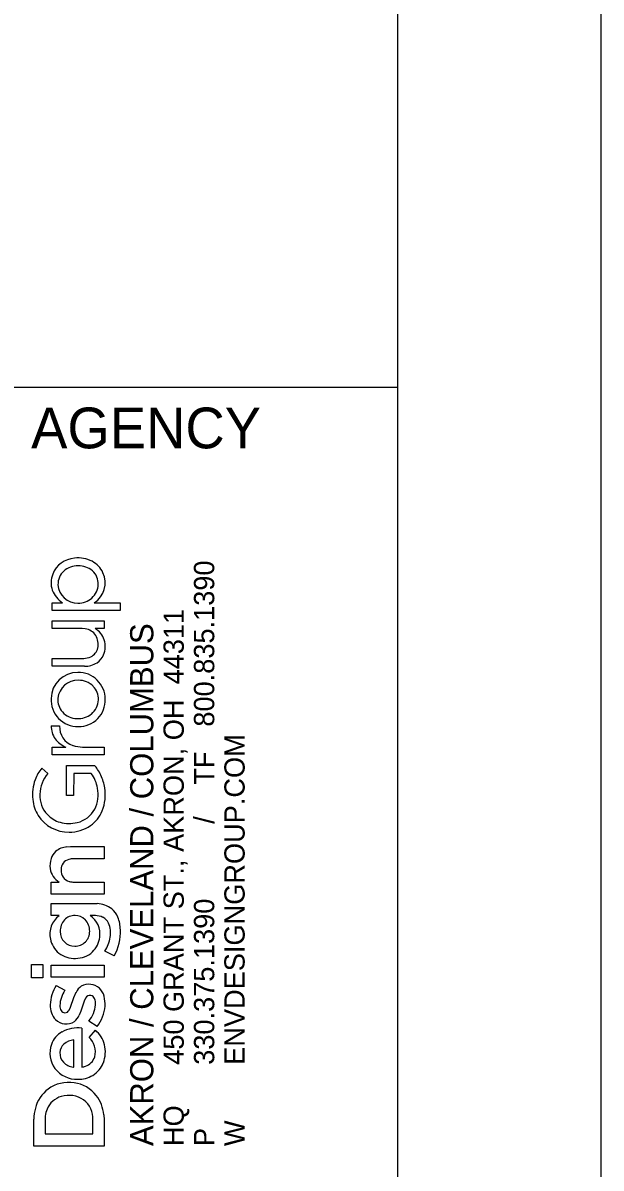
# Model space of a CAD drawing. Extents: x 0 to 34, y 0 to 22.
# Drawn here: x 32.58 to 34, y 2.584 to 5.394 of the extents above; entities that cross this region are included whole.
import ezdxf

# ---------------------------------------------------------------- set-up
doc = ezdxf.new("R2010")
doc.units = 0
for name, color, linetype in [('SH_Border', 7, 'Continuous'), ('SH_Cut_Line', 7, 'Continuous'), ('SH_Data', 7, 'Continuous')]:
    doc.layers.add(name, color=color, linetype=linetype)

msp = doc.modelspace()

# ---------------------------------------------------------------- linework, layer by layer
at = {"layer": 'SH_Border'}
msp.add_line((32, 4.5), (33.5, 4.5), dxfattribs=at)
msp.add_lwpolyline([(1.5, 21.5), (33.5, 21.5), (33.5, 0.5), (1.5, 0.5)], close=True, dxfattribs=at)
at = {"layer": 'SH_Cut_Line'}
msp.add_lwpolyline([(0, 0), (34, 0), (34, 22), (0, 22)], close=True, dxfattribs=at)
at = {"layer": 'SH_Data'}
for p, q in [((32.6515, 3.9521), (32.6515, 3.9711)), ((32.6515, 3.9711), (32.6771, 3.9711)), ((32.7549, 3.9713), (32.8186, 3.9711)), ((32.8186, 3.9711), (32.8184, 3.9521)), ((32.8184, 3.9521), (32.6515, 3.9521)), ((32.6515, 3.908), (32.6515, 3.9267)), ((32.6515, 3.9267), (32.7791, 3.9266)), ((32.7249, 3.908), (32.6515, 3.908)), ((32.7328, 3.9073), (32.7249, 3.908)), ((32.7791, 3.908), (32.7569, 3.908)), ((32.7791, 3.9266), (32.7791, 3.908)), ((32.6515, 3.8344), (32.7291, 3.8345)), ((32.6517, 3.8154), (32.6515, 3.8344)), ((32.7307, 3.8154), (32.6517, 3.8154)), ((32.6493, 3.6691), (32.6698, 3.6691)), ((32.6515, 3.598), (32.6515, 3.617)), ((32.6515, 3.617), (32.6848, 3.617)), ((32.779, 3.598), (32.6515, 3.598)), ((32.726, 3.617), (32.7791, 3.617)), ((32.7791, 3.617), (32.779, 3.598)), ((32.6868, 3.5718), (32.7552, 3.5719)), ((32.6868, 3.4978), (32.6868, 3.5718)), ((32.6264, 3.5655), (32.6411, 3.5524)), ((32.7045, 3.5524), (32.7043, 3.4978)), ((32.7474, 3.5523), (32.7045, 3.5524)), ((32.7043, 3.4978), (32.6868, 3.4978)), ((32.75, 3.5), (32.75, 3.5)), ((32.6878, 3.3722), (32.6963, 3.3727)), ((32.6963, 3.3727), (32.7792, 3.3727)), ((32.7792, 3.3727), (32.7792, 3.3429)), ((32.7792, 3.3429), (32.7048, 3.3428)), ((32.6489, 3.2557), (32.6489, 3.2855)), ((32.6489, 3.2855), (32.669, 3.2855)), ((32.7057, 3.2855), (32.7791, 3.2855)), ((32.7791, 3.2855), (32.7792, 3.2558)), ((32.7792, 3.2558), (32.6489, 3.2557)), ((32.6489, 3.2034), (32.6489, 3.2332)), ((32.6489, 3.2332), (32.7524, 3.2332)), ((32.7524, 3.2332), (32.7619, 3.2329)), ((32.6684, 3.2034), (32.6489, 3.2034)), ((32.7576, 3.2036), (32.7449, 3.2036)), ((32.8036, 3.1049), (32.7812, 3.116)), ((32.6005, 3.0511), (32.6005, 3.0832)), ((32.6005, 3.0832), (32.6289, 3.0832)), ((32.6289, 3.0832), (32.6289, 3.0511)), ((32.6489, 3.0523), (32.6489, 3.0822)), ((32.6489, 3.0822), (32.7792, 3.0822)), ((32.7792, 3.0822), (32.7792, 3.0523)), ((32.6289, 3.0511), (32.6005, 3.0511)), ((32.7792, 3.0523), (32.6489, 3.0523)), ((32.6615, 3.0321), (32.6827, 3.0203)), ((32.7048, 3.0026), (32.7104, 3.0153)), ((32.693, 2.9712), (32.6967, 2.9787)), ((32.6967, 2.9787), (32.7048, 3.0026)), ((32.7298, 2.9933), (32.7221, 2.9688)), ((32.7334, 3.001), (32.7298, 2.9933)), ((32.7221, 2.9688), (32.7182, 2.9592)), ((32.7245, 2.9275), (32.7246, 2.8319)), ((32.7621, 2.9314), (32.742, 2.9447)), ((32.7049, 2.8318), (32.7049, 2.8983)), ((32.7423, 2.9046), (32.7577, 2.922)), ((32.7036, 2.8317), (32.7049, 2.8318)), ((32.6064, 2.638), (32.6064, 2.704)), ((32.6347, 2.7118), (32.6341, 2.7023)), ((32.6341, 2.7023), (32.6341, 2.6684)), ((32.7515, 2.6683), (32.7515, 2.7024)), ((32.7785, 2.715), (32.7792, 2.7021)), ((32.7792, 2.7021), (32.7792, 2.638)), ((32.6341, 2.6684), (32.7515, 2.6683)), ((32.7792, 2.638), (32.6064, 2.638))]:
    msp.add_line(p, q, dxfattribs=at)
for points in [[(32.7549, 3.9713), (32.8186, 3.9711), (32.8184, 3.9521), (32.6515, 3.9521)], [(32.6515, 3.9521), (32.6515, 3.9711), (32.6771, 3.9711)], [(32.7328, 3.9073), (32.7249, 3.908), (32.6515, 3.908), (32.6515, 3.9267), (32.7791, 3.9266), (32.7791, 3.908), (32.7569, 3.908)], [(32.7307, 3.8154), (32.6517, 3.8154), (32.6515, 3.8344), (32.7291, 3.8345)], [(32.6493, 3.6691), (32.6698, 3.6691)], [(32.6515, 3.598), (32.6515, 3.617), (32.6848, 3.617)], [(32.726, 3.617), (32.7791, 3.617), (32.779, 3.598), (32.6515, 3.598)], [(32.7474, 3.5523), (32.7045, 3.5524), (32.7043, 3.4978), (32.6868, 3.4978), (32.6868, 3.5718), (32.7552, 3.5719)], [(32.6264, 3.5655), (32.6411, 3.5524)], [(32.6878, 3.3722), (32.6963, 3.3727), (32.7792, 3.3727), (32.7792, 3.3429), (32.7048, 3.3428)], [(32.6489, 3.2557), (32.6489, 3.2855), (32.669, 3.2855)], [(32.7057, 3.2855), (32.7791, 3.2855), (32.7792, 3.2558), (32.6489, 3.2557)], [(32.6684, 3.2034), (32.6489, 3.2034), (32.6489, 3.2332), (32.7524, 3.2332), (32.7619, 3.2329)], [(32.7576, 3.2036), (32.7449, 3.2036)], [(32.8036, 3.1049), (32.7812, 3.116)], [(32.6615, 3.0321), (32.6827, 3.0203)], [(32.693, 2.9712), (32.6967, 2.9787), (32.7048, 3.0026), (32.7104, 3.0153)], [(32.7334, 3.001), (32.7298, 2.9933), (32.7221, 2.9688), (32.7182, 2.9592)], [(32.7245, 2.9275), (32.7246, 2.8319)], [(32.7621, 2.9314), (32.742, 2.9447)], [(32.7036, 2.8317), (32.7049, 2.8318), (32.7049, 2.8983)], [(32.7423, 2.9046), (32.7577, 2.922)], [(32.7785, 2.715), (32.7792, 2.7021), (32.7792, 2.638), (32.6064, 2.638)], [(32.6064, 2.638), (32.6064, 2.704)], [(32.6347, 2.7118), (32.6341, 2.7023), (32.6341, 2.6684), (32.7515, 2.6683), (32.7515, 2.7024)]]:
    msp.add_lwpolyline(points, dxfattribs=at)
for points in [[(32.6005, 3.0511), (32.6005, 3.0832), (32.6289, 3.0832), (32.6289, 3.0511)], [(32.6489, 3.0523), (32.6489, 3.0822), (32.7792, 3.0822), (32.7792, 3.0523)]]:
    msp.add_lwpolyline(points, close=True, dxfattribs=at)
for centre, radius, start, end in [((32.7108, 4.0182), 0.0624, 93.9866, 158.3119), ((32.7108, 4.0182), 0.0624, 93.9866, 158.3119), ((32.7156, 4.0065), 0.0746, 62.6889, 97.0135), ((32.7156, 4.0065), 0.0746, 62.6889, 97.0135), ((32.7092, 4.0167), 0.0434, 132.3289, 182.0949), ((32.7092, 4.0167), 0.0434, 132.3289, 182.0949), ((32.7138, 4.0102), 0.0513, 87.8965, 131.1812), ((32.7138, 4.0102), 0.0513, 87.8965, 131.1812), ((32.7175, 4.0102), 0.0513, 49.9089, 92.0363), ((32.7175, 4.0102), 0.0513, 49.9089, 92.0363), ((32.7212, 4.0191), 0.0608, 25.0657, 61.9602), ((32.7212, 4.0191), 0.0608, 25.0657, 61.9602), ((32.7215, 4.0173), 0.0433, 358.0487, 47.9447), ((32.7215, 4.0173), 0.0433, 358.0487, 47.9447), ((32.707, 4.0202), 0.0581, 158.656, 198.171), ((32.707, 4.0202), 0.0581, 158.656, 198.171), ((32.7245, 4.02), 0.0574, 301.9776, 25.6418), ((32.7245, 4.02), 0.0574, 301.9776, 25.6418), ((32.7103, 4.0243), 0.0627, 200.8399, 238.0162), ((32.7103, 4.0243), 0.0627, 200.8399, 238.0162), ((32.7135, 4.0181), 0.0478, 183.5974, 271.7045), ((32.7135, 4.0181), 0.0478, 183.5974, 271.7045), ((32.7172, 4.018), 0.0477, 267.3149, 357.4019), ((32.7172, 4.018), 0.0477, 267.3149, 357.4019), ((32.7271, 3.87), 0.0377, 33.5008, 81.3295), ((32.7271, 3.87), 0.0377, 33.5008, 81.3295), ((32.7324, 3.8648), 0.0496, 17.6221, 60.3897), ((32.7324, 3.8648), 0.0496, 17.6221, 60.3897), ((32.7241, 3.8695), 0.0405, 346.5618, 31.7539), ((32.7241, 3.8695), 0.0405, 346.5618, 31.7539), ((32.7234, 3.8641), 0.0584, 339.162, 15.6148), ((32.7234, 3.8641), 0.0584, 339.162, 15.6148), ((32.7337, 3.8662), 0.0304, 294.6321, 348.4863), ((32.7337, 3.8662), 0.0304, 294.6321, 348.4863), ((32.7275, 3.8808), 0.0463, 271.952, 294.0894), ((32.7275, 3.8808), 0.0463, 271.952, 294.0894), ((32.7321, 3.8726), 0.0571, 268.627, 301.4778), ((32.7321, 3.8726), 0.0571, 268.627, 301.4778), ((32.739, 3.859), 0.042, 303.1039, 338.1561), ((32.739, 3.859), 0.042, 303.1039, 338.1561), ((32.7143, 3.7348), 0.0655, 89.4821, 178.7775), ((32.7143, 3.7348), 0.0655, 89.4821, 178.7775), ((32.7158, 3.7341), 0.0662, 0.4227, 90.7613), ((32.7158, 3.7341), 0.0662, 0.4227, 90.7613), ((32.714, 3.7324), 0.0485, 87.6883, 175.017), ((32.714, 3.7324), 0.0485, 87.6883, 175.017), ((32.7166, 3.7304), 0.0505, 44.912, 90.7591), ((32.7166, 3.7304), 0.0505, 44.912, 90.7591), ((32.7196, 3.7345), 0.0455, 358.3228, 43.8349), ((32.7196, 3.7345), 0.0455, 358.3228, 43.8349), ((32.7148, 3.7334), 0.0661, 177.5373, 270.9452), ((32.7148, 3.7334), 0.0661, 177.5373, 270.9452), ((32.7108, 3.7331), 0.0453, 175.5147, 221.4205), ((32.7108, 3.7331), 0.0453, 175.5147, 221.4205), ((32.7167, 3.7327), 0.0654, 269.3083, 1.6791), ((32.7167, 3.7327), 0.0654, 269.3083, 1.6791), ((32.7193, 3.7337), 0.0457, 308.9038, 359.3095), ((32.7193, 3.7337), 0.0457, 308.9038, 359.3095), ((32.714, 3.7373), 0.0505, 222.6626, 268.3733), ((32.714, 3.7373), 0.0505, 222.6626, 268.3733), ((32.7157, 3.7386), 0.0518, 266.5531, 308.6725), ((32.7157, 3.7386), 0.0518, 266.5531, 308.6725), ((32.6988, 3.6666), 0.0495, 177.1621, 216.2802), ((32.6988, 3.6666), 0.0495, 177.1621, 216.2802), ((32.7173, 3.6664), 0.0476, 176.7699, 252.1504), ((32.7173, 3.6664), 0.0476, 176.7699, 252.1504), ((32.7098, 3.6755), 0.0637, 216.9153, 246.8862), ((32.7098, 3.6755), 0.0637, 216.9153, 246.8862), ((32.7269, 3.6917), 0.0747, 251.1388, 269.3469), ((32.7269, 3.6917), 0.0747, 251.1388, 269.3469), ((32.725, 3.5394), 0.0444, 30.9891, 47.161), ((32.725, 3.5394), 0.0444, 30.9891, 47.161), ((32.7016, 3.5019), 0.0986, 139.7948, 159.137), ((32.7016, 3.5019), 0.0986, 139.7948, 159.137), ((32.699, 3.5008), 0.0775, 138.258, 179.7006), ((32.699, 3.5008), 0.0775, 138.258, 179.7006), ((32.6789, 3.501), 0.0856, 10.0751, 36.8319), ((32.6789, 3.501), 0.0856, 10.0751, 36.8319), ((32.6709, 3.5002), 0.1111, 25.3031, 33.9618), ((32.6709, 3.5002), 0.1111, 25.3031, 33.9618), ((32.6704, 3.4999), 0.1117, 8.8034, 25.3348), ((32.6704, 3.4999), 0.1117, 8.8034, 25.3348), ((32.7187, 3.4997), 0.1154, 161.1438, 185.6281), ((32.7187, 3.4997), 0.1154, 161.1438, 185.6281), ((32.6842, 3.5006), 0.0804, 333.4669, 11.0367), ((32.6842, 3.5006), 0.0804, 333.4669, 11.0367), ((32.6756, 3.4998), 0.1065, 338.2887, 9.2855), ((32.6756, 3.4998), 0.1065, 338.2887, 9.2855), ((32.6934, 3.497), 0.0899, 185.5077, 212.0129), ((32.6934, 3.497), 0.0899, 185.5077, 212.0129), ((32.6881, 3.4973), 0.0668, 176.6658, 223.6912), ((32.6881, 3.4973), 0.0668, 176.6658, 223.6912), ((32.6987, 3.4955), 0.0652, 282.8815, 331.8147), ((32.6987, 3.4955), 0.0652, 282.8815, 331.8147), ((32.6984, 3.4917), 0.0824, 305.0306, 337.6757), ((32.6984, 3.4917), 0.0824, 305.0306, 337.6757), ((32.6921, 3.4975), 0.0891, 212.7022, 270.714), ((32.6921, 3.4975), 0.0891, 212.7022, 270.714), ((32.6905, 3.5001), 0.0704, 224.0215, 253.88), ((32.6905, 3.5001), 0.0704, 224.0215, 253.88), ((32.6932, 3.5125), 0.0831, 254.4535, 283.9512), ((32.6932, 3.5125), 0.0831, 254.4535, 283.9512), ((32.6943, 3.4998), 0.0914, 269.3273, 304.1963), ((32.6943, 3.4998), 0.0914, 269.3273, 304.1963), ((32.6922, 3.3225), 0.0499, 94.9706, 130.2248), ((32.6922, 3.3225), 0.0499, 94.9706, 130.2248), ((32.6869, 3.3309), 0.0402, 132.2238, 161.6823), ((32.6869, 3.3309), 0.0402, 132.2238, 161.6823), ((32.7022, 3.3264), 0.056, 162.274, 187.7917), ((32.7022, 3.3264), 0.056, 162.274, 187.7917), ((32.6937, 3.3262), 0.0476, 188.9646, 238.6987), ((32.6937, 3.3262), 0.0476, 188.9646, 238.6987), ((32.7008, 3.3138), 0.0276, 175.5844, 255.1382), ((32.7008, 3.3138), 0.0276, 175.5844, 255.1382), ((32.6983, 3.3169), 0.025, 103.6868, 182.214), ((32.6983, 3.3169), 0.025, 103.6868, 182.214), ((32.7045, 3.2968), 0.046, 89.6051, 105.3303), ((32.7045, 3.2968), 0.046, 89.6051, 105.3303), ((32.7053, 3.3277), 0.0421, 254.0891, 270.5284), ((32.7053, 3.3277), 0.0421, 254.0891, 270.5284), ((32.7591, 3.1679), 0.065, 53.4034, 87.4906), ((32.7591, 3.1679), 0.065, 53.4034, 87.4906), ((32.7029, 3.1581), 0.0569, 127.3748, 192.2247), ((32.7029, 3.1581), 0.0569, 127.3748, 192.2247), ((32.7069, 3.1693), 0.0346, 88.473, 136.4256), ((32.7069, 3.1693), 0.0346, 88.473, 136.4256), ((32.7081, 3.1696), 0.0342, 44.2719, 90.4762), ((32.7081, 3.1696), 0.0342, 44.2719, 90.4762), ((32.7142, 3.1583), 0.0547, 352.1125, 55.923), ((32.7142, 3.1583), 0.0547, 352.1125, 55.923), ((32.7567, 3.1572), 0.0463, 65.0169, 88.8011), ((32.7567, 3.1572), 0.0463, 65.0169, 88.8011), ((32.7652, 3.1804), 0.0514, 21.6075, 50.5577), ((32.7652, 3.1804), 0.0514, 21.6075, 50.5577), ((32.7114, 3.166), 0.0401, 137.4674, 182.3324), ((32.7114, 3.166), 0.0401, 137.4674, 182.3324), ((32.7037, 3.166), 0.04, 358.5714, 43.5376), ((32.7037, 3.166), 0.04, 358.5714, 43.5376), ((32.7626, 3.1716), 0.0309, 26.2681, 63.803), ((32.7626, 3.1716), 0.0309, 26.2681, 63.803), ((32.7357, 3.1615), 0.0595, 349.3073, 23.4307), ((32.7357, 3.1615), 0.0595, 349.3073, 23.4307), ((32.7307, 3.1671), 0.0884, 1.1514, 21.3627), ((32.7307, 3.1671), 0.0884, 1.1514, 21.3627), ((32.7065, 3.1637), 0.0351, 178.8821, 271.0837), ((32.7065, 3.1637), 0.0351, 178.8821, 271.0837), ((32.7082, 3.164), 0.0355, 268.2788, 1.5502), ((32.7082, 3.164), 0.0355, 268.2788, 1.5502), ((32.7099, 3.1571), 0.0589, 313.742, 353.8554), ((32.7099, 3.1571), 0.0589, 313.742, 353.8554), ((32.7074, 3.1633), 0.0877, 327.3149, 351.5748), ((32.7074, 3.1633), 0.0877, 327.3149, 351.5748), ((32.7054, 3.1624), 0.1138, 329.6388, 3.26), ((32.7054, 3.1624), 0.1138, 329.6388, 3.26), ((32.7046, 3.157), 0.0584, 190.7518, 231.2892), ((32.7046, 3.157), 0.0584, 190.7518, 231.2892), ((32.7063, 3.1611), 0.0627, 232.4606, 272.5902), ((32.7063, 3.1611), 0.0627, 232.4606, 272.5902), ((32.7095, 3.159), 0.0605, 269.6361, 312.7088), ((32.7095, 3.159), 0.0605, 269.6361, 312.7088), ((32.7406, 3.0026), 0.0326, 80.1719, 122.5197), ((32.7406, 3.0026), 0.0326, 80.1719, 122.5197), ((32.7428, 2.9982), 0.0367, 47.7934, 84.6892), ((32.7428, 2.9982), 0.0367, 47.7934, 84.6892), ((32.7364, 2.9826), 0.0897, 146.531, 178.7571), ((32.7364, 2.9826), 0.0897, 146.531, 178.7571), ((32.7452, 2.9789), 0.0749, 146.5112, 176.9101), ((32.7452, 2.9789), 0.0749, 146.5112, 176.9101), ((32.7466, 2.9971), 0.0405, 125.5118, 153.4159), ((32.7466, 2.9971), 0.0405, 125.5118, 153.4159), ((32.7438, 2.9963), 0.0114, 76.6609, 155.7053), ((32.7438, 2.9963), 0.0114, 76.6609, 155.7053), ((32.744, 2.9951), 0.0126, 21.5098, 78.5262), ((32.744, 2.9951), 0.0126, 21.5098, 78.5262), ((32.7379, 2.9946), 0.0427, 14.9966, 46.2063), ((32.7379, 2.9946), 0.0427, 14.9966, 46.2063), ((32.6967, 2.9824), 0.0501, 177.5366, 222.7932), ((32.6967, 2.9824), 0.0501, 177.5366, 222.7932), ((32.6931, 2.9823), 0.0228, 178.4747, 211.0868), ((32.6931, 2.9823), 0.0228, 178.4747, 211.0868), ((32.6825, 2.9915), 0.0757, 321.811, 354.7969), ((32.6825, 2.9915), 0.0757, 321.811, 354.7969), ((32.7259, 2.9877), 0.0321, 354.5726, 22.068), ((32.7259, 2.9877), 0.0321, 354.5726, 22.068), ((32.6895, 2.9882), 0.0922, 321.9777, 355.8738), ((32.6895, 2.9882), 0.0922, 321.9777, 355.8738), ((32.7104, 2.9867), 0.0712, 355.8306, 15.3914), ((32.7104, 2.9867), 0.0712, 355.8306, 15.3914), ((32.6833, 2.9767), 0.0115, 212.2368, 268.3777), ((32.6833, 2.9767), 0.0115, 212.2368, 268.3777), ((32.6834, 2.9759), 0.0107, 267.716, 333.7337), ((32.6834, 2.9759), 0.0107, 267.716, 333.7337), ((32.681, 2.9758), 0.0408, 308.0877, 335.9874), ((32.681, 2.9758), 0.0408, 308.0877, 335.9874), ((32.686, 2.9753), 0.0375, 225.9854, 302.4797), ((32.686, 2.9753), 0.0375, 225.9854, 302.4797), ((32.7152, 2.8441), 0.0838, 83.615, 118.2876), ((32.7152, 2.8441), 0.0838, 83.615, 118.2876), ((32.7024, 2.8691), 0.0558, 118.8308, 160.6244), ((32.7024, 2.8691), 0.0558, 118.8308, 160.6244), ((32.7079, 2.8561), 0.0424, 94.008, 130.8817), ((32.7079, 2.8561), 0.0424, 94.008, 130.8817), ((32.7038, 2.8656), 0.0549, 19.0357, 45.4406), ((32.7038, 2.8656), 0.0549, 19.0357, 45.4406), ((32.7174, 2.8717), 0.0644, 13.5336, 51.3615), ((32.7174, 2.8717), 0.0644, 13.5336, 51.3615), ((32.7104, 2.8661), 0.0644, 160.5201, 215.7831), ((32.7104, 2.8661), 0.0644, 160.5201, 215.7831), ((32.7017, 2.865), 0.0311, 175.0013, 223.283), ((32.7017, 2.865), 0.0311, 175.0013, 223.283), ((32.7005, 2.8663), 0.0298, 132.9851, 177.179), ((32.7005, 2.8663), 0.0298, 132.9851, 177.179), ((32.7107, 2.8697), 0.047, 344.6059, 17.007), ((32.7107, 2.8697), 0.047, 344.6059, 17.007), ((32.7064, 2.8692), 0.0758, 339.3542, 13.3785), ((32.7064, 2.8692), 0.0758, 339.3542, 13.3785), ((32.7089, 2.8736), 0.0423, 225.0619, 262.7974), ((32.7089, 2.8736), 0.0423, 225.0619, 262.7974), ((32.7224, 2.8671), 0.035, 288.0077, 343.5508), ((32.7224, 2.8671), 0.035, 288.0077, 343.5508), ((32.7189, 2.8652), 0.0626, 300.9427, 338.7323), ((32.7189, 2.8652), 0.0626, 300.9427, 338.7323), ((32.7125, 2.8705), 0.0687, 217.7452, 271.6543), ((32.7125, 2.8705), 0.0687, 217.7452, 271.6543), ((32.7155, 2.8724), 0.0706, 269.2048, 300.3341), ((32.7155, 2.8724), 0.0706, 269.2048, 300.3341), ((32.7247, 2.8522), 0.0202, 269.7003, 294.8711), ((32.7247, 2.8522), 0.0202, 269.7003, 294.8711), ((32.6923, 2.7079), 0.0864, 81.194, 125.9984), ((32.6923, 2.7079), 0.0864, 81.194, 125.9984), ((32.6946, 2.7113), 0.0827, 37.8521, 82.402), ((32.6946, 2.7113), 0.0827, 37.8521, 82.402), ((32.6939, 2.7089), 0.0865, 127.2362, 165.148), ((32.6939, 2.7089), 0.0865, 127.2362, 165.148), ((32.6889, 2.7078), 0.054, 106.1881, 157.3861), ((32.6889, 2.7078), 0.054, 106.1881, 157.3861), ((32.6928, 2.6986), 0.0639, 55.6727, 107.2093), ((32.6928, 2.6986), 0.0639, 55.6727, 107.2093), ((32.6859, 2.7057), 0.0931, 5.7333, 37.304), ((32.6859, 2.7057), 0.0931, 5.7333, 37.304), ((32.7143, 2.7028), 0.1078, 164.7861, 179.3704), ((32.7143, 2.7028), 0.1078, 164.7861, 179.3704), ((32.6983, 2.7039), 0.0641, 157.3571, 172.9275), ((32.6983, 2.7039), 0.0641, 157.3571, 172.9275), ((32.6929, 2.705), 0.0587, 357.4662, 52.2665), ((32.6929, 2.705), 0.0587, 357.4662, 52.2665)]:
    msp.add_arc(centre, radius, start, end, dxfattribs=at)

# ---------------------------------------------------------------- texts
msp.add_text('DESIGN AGENCY', height=0.1, dxfattribs=at).set_placement((32.05, 4.35))
for s, height, p in [('800.835.1390', 0.049846, (33.0497, 3.6671)), ('450 GRANT ST., AKRON, OH  44311', 0.049846, (32.9749, 2.8374)), ('AKRON / CLEVELAND / COLUMBUS', 0.056969, (32.9001, 2.638)), ('ENVDESIGNGROUP.COM', 0.049846, (33.1244, 2.8374)), ('TF', 0.04985, (33.0497, 3.5246)), ('/  ', 0.04985, (33.0497, 3.4288)), ('330.375.1390', 0.049846, (33.0497, 2.8374)), ('HQ ', 0.04985, (32.9749, 2.638)), ('W', 0.0498, (33.1244, 2.638)), ('P', 0.0498, (33.0497, 2.638))]:
    msp.add_text(s, height=height, rotation=90, dxfattribs=at).set_placement(p)

doc.saveas('drawing.dxf')
